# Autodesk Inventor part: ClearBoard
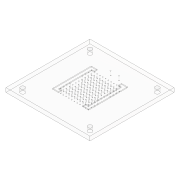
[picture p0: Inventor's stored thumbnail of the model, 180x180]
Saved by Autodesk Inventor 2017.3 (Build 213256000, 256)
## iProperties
Part Number: ClearBoard
Material: PET プラスチック
Document SubType Name: Modeling
Designer: kyushu-hep
Density: 1.541 g/cm^3
Appearance: ポリカーボネート - クリア
Author: kyushu-hep
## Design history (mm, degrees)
sketch "スケッチ1"
  geometry: L1 (50, -50)-(-50, -50); L2 (-50, -50)-(-50, 50); L3 (-50, 50)-(50, 50); L4 (50, 50)-(50, -50); L5 (50, -50)-(-50, 50); L6 (-50, -50)-(50, 50); 1 further point
  constraints: 12 end point, 2 midpoint, 2 parallel, 1 horizontal, 1 perpendicular
  dimensions: "d0" = 100 distance of L2.end L3.end; "d1" = 100 distance of L1.end L2.end
extrude "押し出し1" new body sketch "スケッチ1" distance "d2" = 5; taper "d3" = 0 deg
sketch "スケッチ2"
  geometry: L1 (-100, 50)-(-100, -50); L2 (-100, -50)-(100, -50); C1 r 0.5 at (-5.05, 29.5); C2 r 0.5 at (5.05, 29.5); 2 further points
  constraints: 4 end point, 2 centre point
  dimensions: "d4" = 1 diameter of C1; "d5" = 1 diameter of C2; "d6" = 10.1 distance of C2.centre C1.centre; "d7" = 29.5 vertical distance of point (0, 0) C2.centre; "d8" = 5.05 horizontal distance of C1.centre point (0, 0)
extrude "押し出し2" cut sketch "スケッチ2" distance "d9" = 5; taper "d10" = 0 deg
sketch "スケッチ3"
  geometry: C1 r 2.5 at (-40, 40); C2 r 2.5 at (40, 40); C3 r 2.5 at (-40, -40); C4 r 2.5 at (40, -40); 1 further point
  constraints: 4 centre point
  dimensions: "d11" = 5 diameter of C1; "d14" = 40 horizontal distance of C1.centre point (0, 0); "d15" = 40 horizontal distance of C1.centre point (0, 0); "d18" = 5 diameter of C2; "d19" = 40 horizontal distance of point (0, 0) C2.centre; "d20" = 40 horizontal distance of C2.centre point (0, 0); "d21" = 5 diameter of C3; "d22" = 40 horizontal distance of point (0, 0) C3.centre; "d23" = 40 horizontal distance of point (0, 0) C3.centre; "d24" = 5 diameter of C4; "d25" = 40 horizontal distance of point (0, 0) C4.centre; "d26" = 40 horizontal distance of point (0, 0) C4.centre
extrude "押し出し3" cut sketch "スケッチ3" distance "d27" = 5; taper "d28" = 0 deg
feature "ねじ1" dims "d29" = 10, "d30" = 0
feature "ねじ2" dims "d31" = 10, "d32" = 0
feature "ねじ3" dims "d33" = 10, "d34" = 0
feature "ねじ4" dims "d35" = 10, "d36" = 0
sketch "スケッチ5"
  geometry: L1 (17.5, -19.5)-(-17.5, -19.5); L2 (-17.5, -19.5)-(-17.5, 19.5); L3 (-17.5, 19.5)-(17.5, 19.5); L4 (17.5, 19.5)-(17.5, -19.5); L5 (17.5, -19.5)-(-17.5, 19.5); L6 (-17.5, -19.5)-(17.5, 19.5); C1 r 0.5 at (-16.5, 18.5); C2 r 0.5 at (-13.2, 18.5); C3 r 0.5 at (-9.9, 18.5); C4 r 0.5 at (-6.6, 18.5); C5 r 0.5 at (-3.3, 18.5); C6 r 0.5 at (0, 18.5); C7 r 0.5 at (3.3, 18.5); C8 r 0.5 at (6.6, 18.5); C9 r 0.5 at (9.9, 18.5); C10 r 0.5 at (13.2, 18.5); C11 r 0.5 at (-16.5, 14.8); C12 r 0.5 at (-13.2, 14.8); C13 r 0.5 at (-9.9, 14.8); C14 r 0.5 at (-6.6, 14.8); C15 r 0.5 at (-3.3, 14.8); C16 r 0.5 at (0, 14.8); C17 r 0.5 at (3.3, 14.8); C18 r 0.5 at (6.6, 14.8); C19 r 0.5 at (9.9, 14.8); C20 r 0.5 at (13.2, 14.8); C21 r 0.5 at (16.5, 18.5); C22 r 0.5 at (16.5, 14.8); C23 r 0.5 at (-16.5, 11.1); C24 r 0.5 at (-13.2, 11.1); C25 r 0.5 at (-9.9, 11.1); C26 r 0.5 at (-6.6, 11.1); C27 r 0.5 at (-3.3, 11.1); C28 r 0.5 at (0, 11.1); C29 r 0.5 at (3.3, 11.1); C30 r 0.5 at (6.6, 11.1); C31 r 0.5 at (9.9, 11.1); C32 r 0.5 at (13.2, 11.1); C33 r 0.5 at (16.5, 11.1); C34 r 0.5 at (-16.5, 7.4); C35 r 0.5 at (-13.2, 7.4); C36 r 0.5 at (-9.9, 7.4); C37 r 0.5 at (-6.6, 7.4); C38 r 0.5 at (-3.3, 7.4); C39 r 0.5 at (0, 7.4); C40 r 0.5 at (3.3, 7.4); C41 r 0.5 at (6.6, 7.4); C42 r 0.5 at (9.9, 7.4); C43 r 0.5 at (13.2, 7.4); C44 r 0.5 at (16.5, 7.4); C45 r 0.5 at (-16.5, 3.7); C46 r 0.5 at (-13.2, 3.7); C47 r 0.5 at (-9.9, 3.7); C48 r 0.5 at (-6.6, 3.7); C49 r 0.5 at (-3.3, 3.7); C50 r 0.5 at (0, 3.7); C51 r 0.5 at (3.3, 3.7); C52 r 0.5 at (6.6, 3.7); C53 r 0.5 at (9.9, 3.7); C54 r 0.5 at (13.2, 3.7); C55 r 0.5 at (16.5, 3.7); C56 r 0.5 at (-16.5, 0); C57 r 0.5 at (-13.2, 0); C58 r 0.5 at (-9.9, 0); C59 r 0.5 at (-6.6, 0); C60 r 0.5 at (-3.3, 0); C61 r 0.5 at (0, 0); C62 r 0.5 at (3.3, 0); C63 r 0.5 at (6.6, 0); C64 r 0.5 at (9.9, 0)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; 1 further point
  constraints: 121 centre point, 12 end point, 2 horizontal, 2 midpoint, 2 parallel, 1 perpendicular, 1 vertical, 240 other
  dimensions: "d58" = 35 distance of L2.end L3.end; "d59" = 39 distance of L3.end L1.start; "d60" = 1 diameter of C1; "d61" = 16.5 horizontal distance of point (0, 0) C1.centre; "d62" = 18.5 vertical distance of point (0, 0) C1.centre; "d65" = 3.3 distance of C1.centre C2.centre; "d68" = 3.7 distance of C1.centre C11.centre
sketch "スケッチ6"
  geometry: L1 (-17.5, 23)-(-21.5, 23); L2 (-21.5, 23)-(-21.5, -23); L3 (-21.5, -23)-(-17.5, -23); L4 (-17.5, -23)-(-17.5, 23); L5 (17.5, -23)-(21.5, -23); L6 (21.5, -23)-(21.5, 23); L7 (21.5, 23)-(17.5, 23); L8 (17.5, 23)-(17.5, -23); L9 (-17.5, 23)-(-14.5, 23); L10 (-14.5, 23)-(-14.5, 19.5); L11 (-14.5, 19.5)-(-17.5, 19.5); L12 (-17.5, 19.5)-(-17.5, 23); L13 (-17.5, -19.5)-(-14.5, -19.5); L14 (-14.5, -19.5)-(-14.5, -23); L15 (-14.5, -23)-(-17.5, -23); L16 (-17.5, -23)-(-17.5, -19.5); L17 (17.5, 19.5)-(14.5, 19.5); L18 (14.5, 19.5)-(14.5, 23); L19 (14.5, 23)-(17.5, 23); L20 (17.5, 23)-(17.5, 19.5); L21 (17.5, -23)-(14.5, -23); L22 (14.5, -23)-(14.5, -19.5); L23 (14.5, -19.5)-(17.5, -19.5); L24 (17.5, -19.5)-(17.5, -23); 1 further point
  constraints: 48 end point, 12 parallel, 6 horizontal, 6 perpendicular, 4 collinear, 4 equal length, 3 point on line
  dimensions: "d75" = 17.5 distance from line of L4 point (0, 0); "d76" = 23 distance from line of point (0, 0) L1; "d77" = 46 distance of L1.end L2.end; "d78" = 17.5 distance from line of L8 point (0, 0); "d79" = 4 distance of L1.start L1.end; "d82" = 3 distance of L10.end L11.end; "d83" = 3.5 distance of L9.end L10.end; "d85" = 3 distance of L18.end L19.end; "d86" = 3 distance of L22.end L23.end
extrude "押し出し9" cut sketch "スケッチ6" distance "d87" = 1; taper "d88" = 0 deg
extrude "押し出し10" cut sketch "スケッチ5" distance "d89" = 10; taper "d90" = 0 deg
node "ソリッド1"
